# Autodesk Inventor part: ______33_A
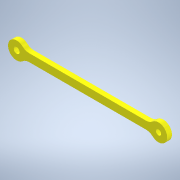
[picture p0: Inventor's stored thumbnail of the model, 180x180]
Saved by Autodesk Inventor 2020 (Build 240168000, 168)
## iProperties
Created: 2017-09
Part Number: ______33_A
Material: Générique
Document SubType Name: Modeling
Designer: bruno
Density: 1 g/cm^3
Appearance: Jaune
Mass: 7.52193 g
Surface Area: 49.6725 cm^2
Volume: 7.52193 cm^3
Sending System: SolidWorks 2016
Author: bruno
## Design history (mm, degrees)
feature "Importée1"
node "Solide1"
